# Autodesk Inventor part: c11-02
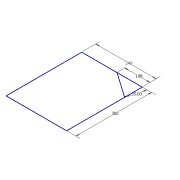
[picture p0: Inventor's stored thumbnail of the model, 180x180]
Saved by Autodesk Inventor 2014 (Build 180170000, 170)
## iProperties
Created: 2011-01
Part Number: c11-02
Material: Aluminum 6061
Document SubType Name: Sheet Metal
Designer: Thom Tremblay
Density: 2.71 g/cm^3
Sheet Metal Rule: Aluminum 3 mm
Appearance: Galvanized
Author: Thom Tremblay
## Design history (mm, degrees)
sketch "Sketch1"
  geometry: L1 (0, 0)-(240, 0); L2 (240, 0)-(240, 300); L3 (240, 300)-(0, 300); L4 (0, 300)-(0, 0); L5 (140, 300)-(240, 229.979)
  constraints: 10 end point, 2 parallel, 2 point on line, 1 horizontal, 1 perpendicular
  dimensions: "d0" = 240 distance of L3.end L2.end; "d1" = 300 distance of L2.end L1.end; "d2" = 35 deg angle of L3 L5; "d3" = 100 distance from line of L2 L5.start
other parameters: "Thickness" = 3 (derived), "BendRadius" = 2 (derived), "BendReliefWidth" = 3 (= Thickness), "BendReliefDepth" = 1.5 (= 0.5 x Thickness), "CornerReliefSize" = 12 (= 4 x Thickness), "SeamGap" = 0.01, "MinimumRemnant" = 6 (= 2 x Thickness), "TransitionRadius" = 2 (= BendRadius), "JacobiRadiusSize" = 2 (= BendRadius), "GapSize" = 1.5 (= 0.5 x Thickness)
